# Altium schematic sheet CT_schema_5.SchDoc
size 405 x 311 mm
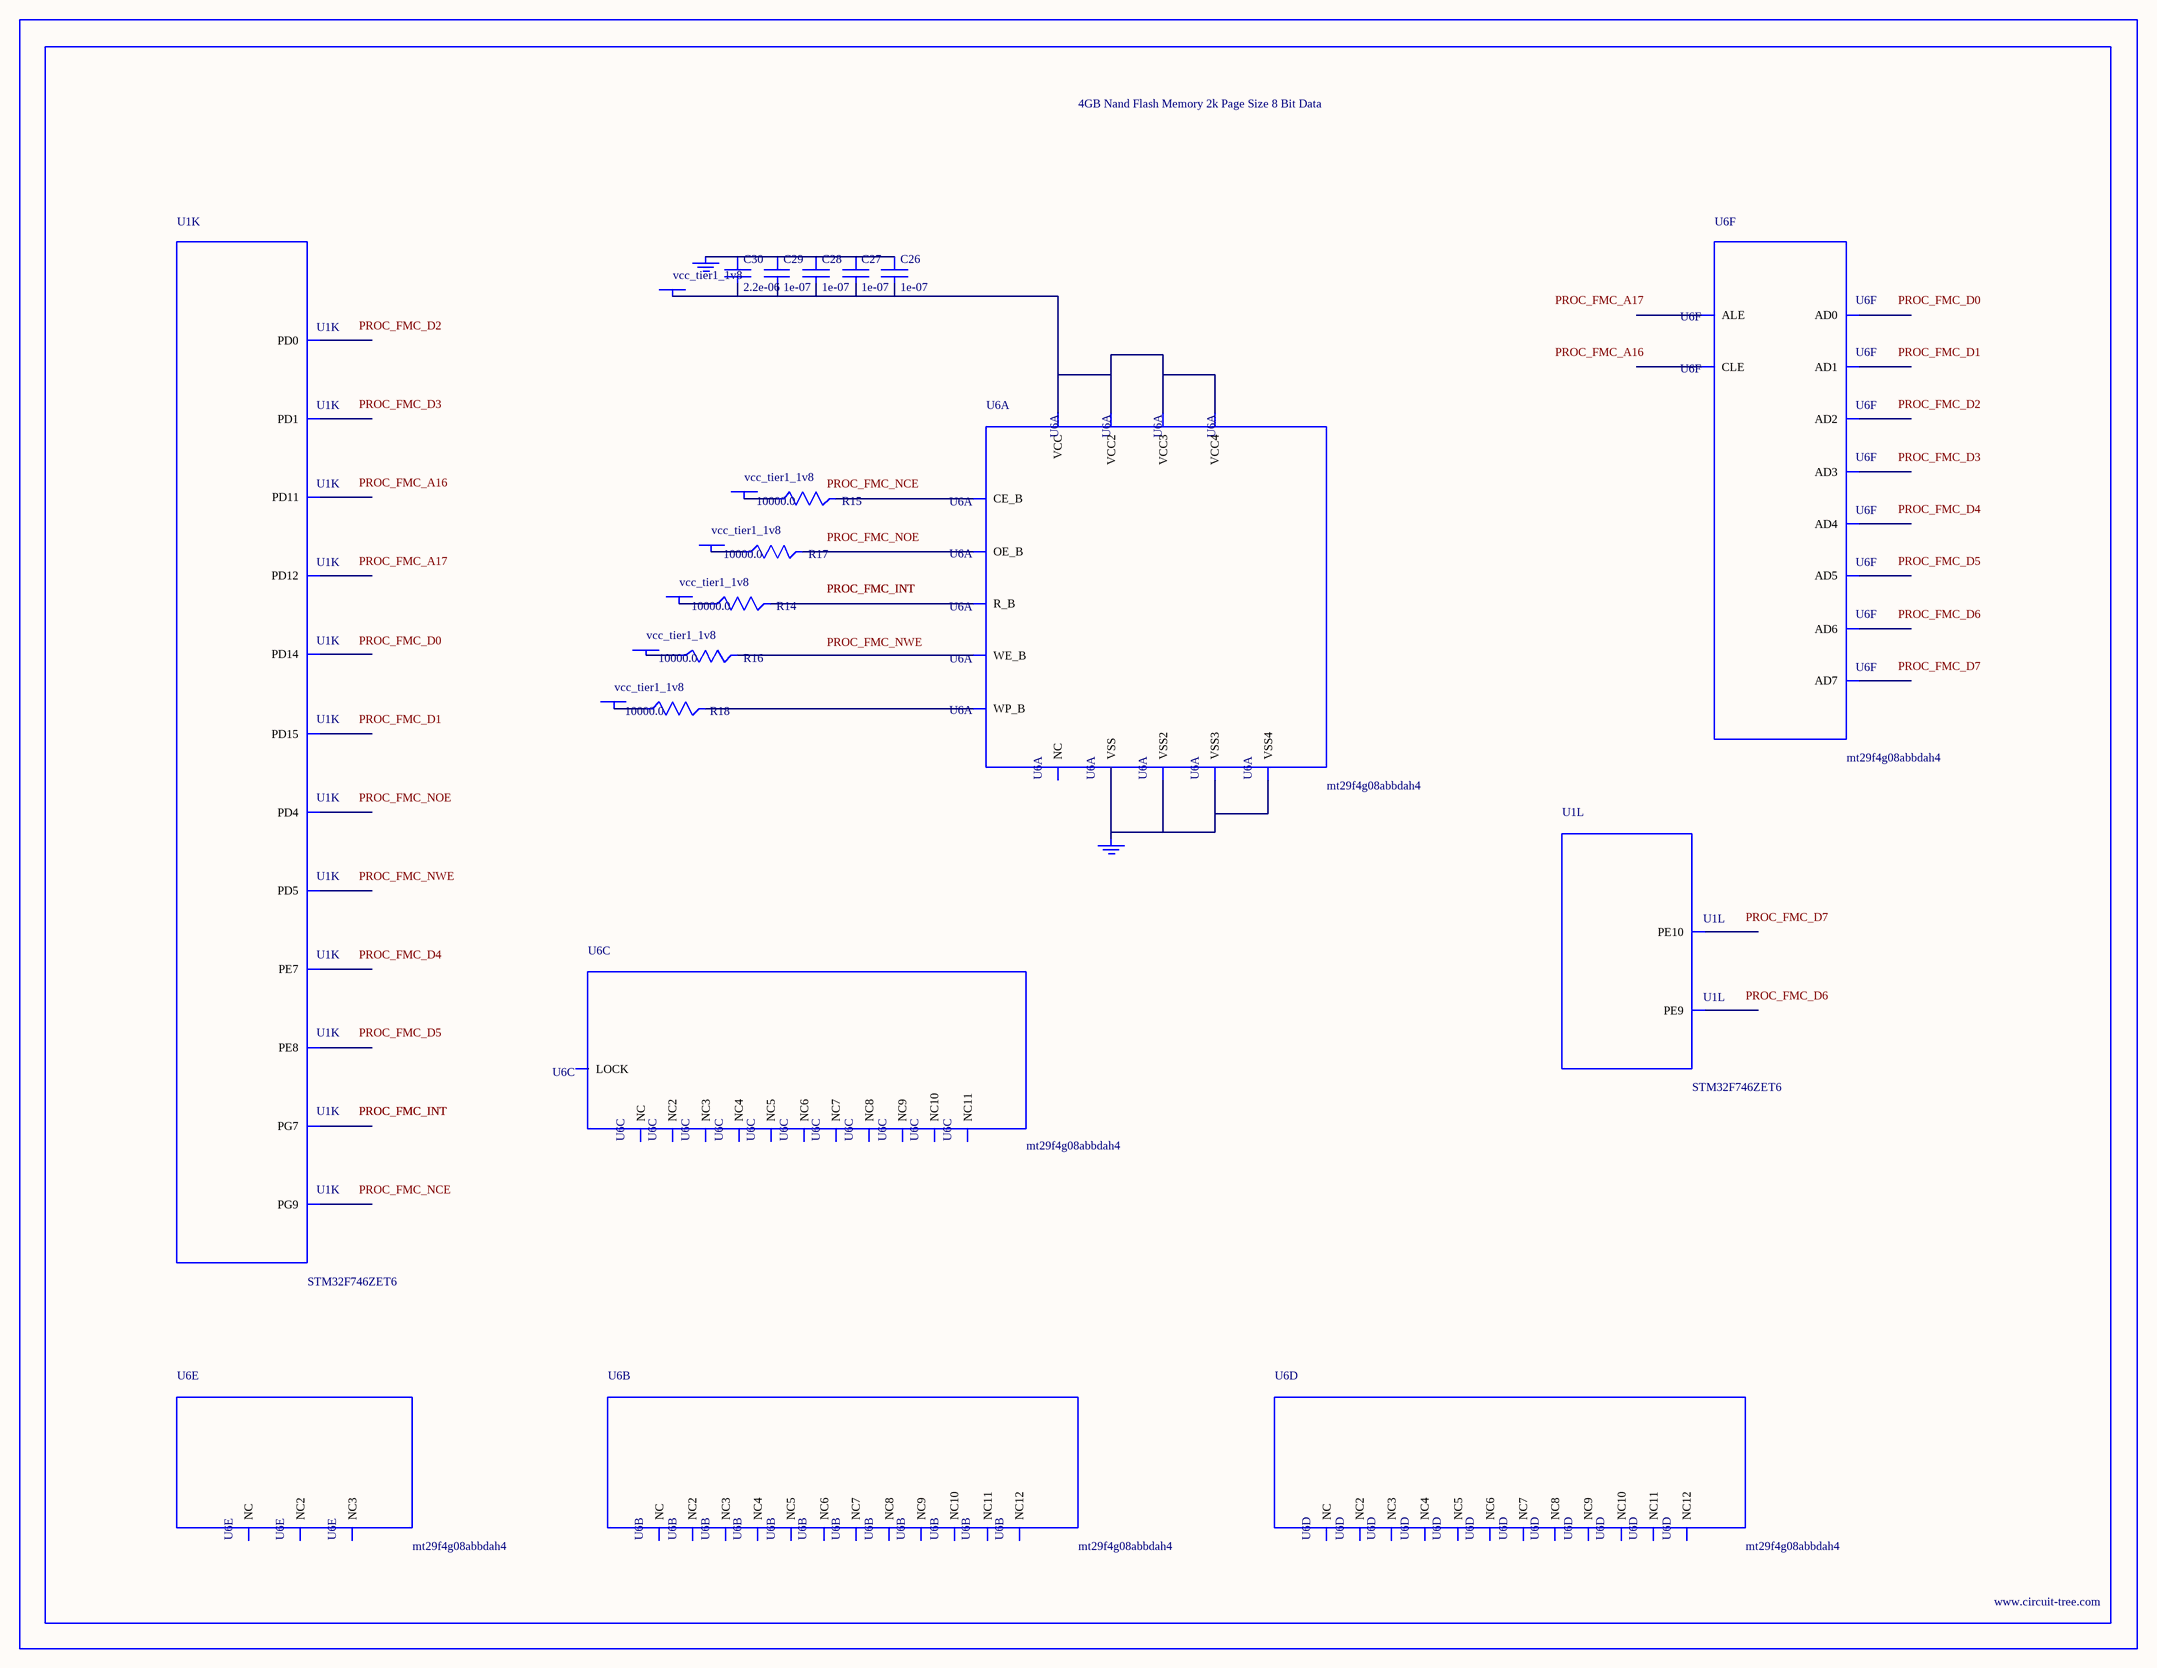
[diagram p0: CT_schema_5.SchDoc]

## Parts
BORDER4  (no value)
C26  1e-07  [C0402]
C27  1e-07  [C0402]
C28  1e-07  [C0402]
C29  1e-07  [C0402]
C30  2.2e-06  [C0603]
GND_INSTANCE_4_0  (no value)
GND_INSTANCE_4_1  (no value)
POWER_INSTANCE_4_0  vcc_tier1_1v8
POWER_INSTANCE_4_1  vcc_tier1_1v8
POWER_INSTANCE_4_2  vcc_tier1_1v8
POWER_INSTANCE_4_3  vcc_tier1_1v8
POWER_INSTANCE_4_4  vcc_tier1_1v8
POWER_INSTANCE_4_5  vcc_tier1_1v8
R14  10000.0  [R0603]
R15  10000.0  [R0603]
R16  10000.0  [R0603]
R17  10000.0  [R0603]
R18  10000.0  [R0603]
U1  STM32F746ZET6  [LQFP144]  (parts K,L of 13)
U6  mt29f4g08abbdah4  [VFBGA-63]  (parts A,B,C,D,E,F of 6)

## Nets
NetC26_1: C26.1 C27.1 C28.1 C29.1 C30.1 GND_INSTANCE_4_0.0(GND)
NetC26_2: C26.2 C27.2 C28.2 C29.2 C30.2 POWER_INSTANCE_4_0.0(PWR) U6.D3(VCC) U6.G4(VCC2) U6.H8(VCC3) U6.J6(VCC4)
NetGND_INSTANCE_4_1_0: GND_INSTANCE_4_1.0(GND) U6.C5(VSS) U6.F7(VSS2) U6.K3(VSS3) U6.K8(VSS4)
NetPOWER_INSTANCE_4_1_0: POWER_INSTANCE_4_1.0(PWR) R14.1
NetPOWER_INSTANCE_4_2_0: POWER_INSTANCE_4_2.0(PWR) R15.1
NetPOWER_INSTANCE_4_3_0: POWER_INSTANCE_4_3.0(PWR) R16.1
NetPOWER_INSTANCE_4_4_0: POWER_INSTANCE_4_4.0(PWR) R17.1
NetPOWER_INSTANCE_4_5_0: POWER_INSTANCE_4_5.0(PWR) R18.1
NetR14_2: R14.2 U6.C8(R_B)
NetR15_2: R15.2 U6.C6(CE_B)
NetR16_2: R16.2 U6.C7(WE_B)
NetR17_2: R17.2 U6.D4(OE_B)
NetR18_2: R18.2 U6.C3(WP_B)

Not connected (* = marked no-connect by the designer): U1 58(PE7) 59(PE8) 60(PE9) 63(PE10) 80(PD11) 81(PD12) 85(PD14) 86(PD15) 92(PG7) 114(PD0) 115(PD1) 118(PD4) 119(PD5) 124(PG9); U6 A1(NC) A2(NC3) A9(NC4) A10(NC2) B1(NC5) B9(NC7) B10(NC6) C4(ALE) D5(CLE) D6(NC8) D7(NC9) D8(NC10) E3(NC11) E4(NC12) E5(NC) E6(NC2) E7(NC3) E8(NC4) F3(NC5) F4(NC6) F5(NC7) F6(NC8) F8(NC9) G3(NC) G5(LOCK) G6(NC10) G7(NC11) G8(NC) H3(NC2) H4(AD0) H5(NC3) H6(NC4) H7(NC5) J3(NC6) J4(AD1) J5(NC7) J7(AD5) J8(AD7) K4(AD2) K5(AD3) K6(AD4) K7(AD6) L1(NC8) L2(NC10) L9(NC11) L10(NC9) M1(NC12) M2(NC2) M9(NC3) M10(NC)

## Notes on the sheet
- Labels drawn without touching a wire or pin: PROC_FMC_A16, PROC_FMC_A17, PROC_FMC_D0, PROC_FMC_D1, PROC_FMC_D2, PROC_FMC_D3, PROC_FMC_D4, PROC_FMC_D5, PROC_FMC_D6, PROC_FMC_D7, PROC_FMC_NCE, PROC_FMC_NOE, PROC_FMC_NWE

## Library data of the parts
BORDER4 = BORDER_PAGE4
C26-C29 = C0402C104K3RACTU
C30 = C0603C225K8RACTU
GND_INSTANCE_4_0 GND_INSTANCE_4_1 = GND
POWER_INSTANCE_4_0-POWER_INSTANCE_4_5 = PWR
R14-R18 = RC0603JR-0710KL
